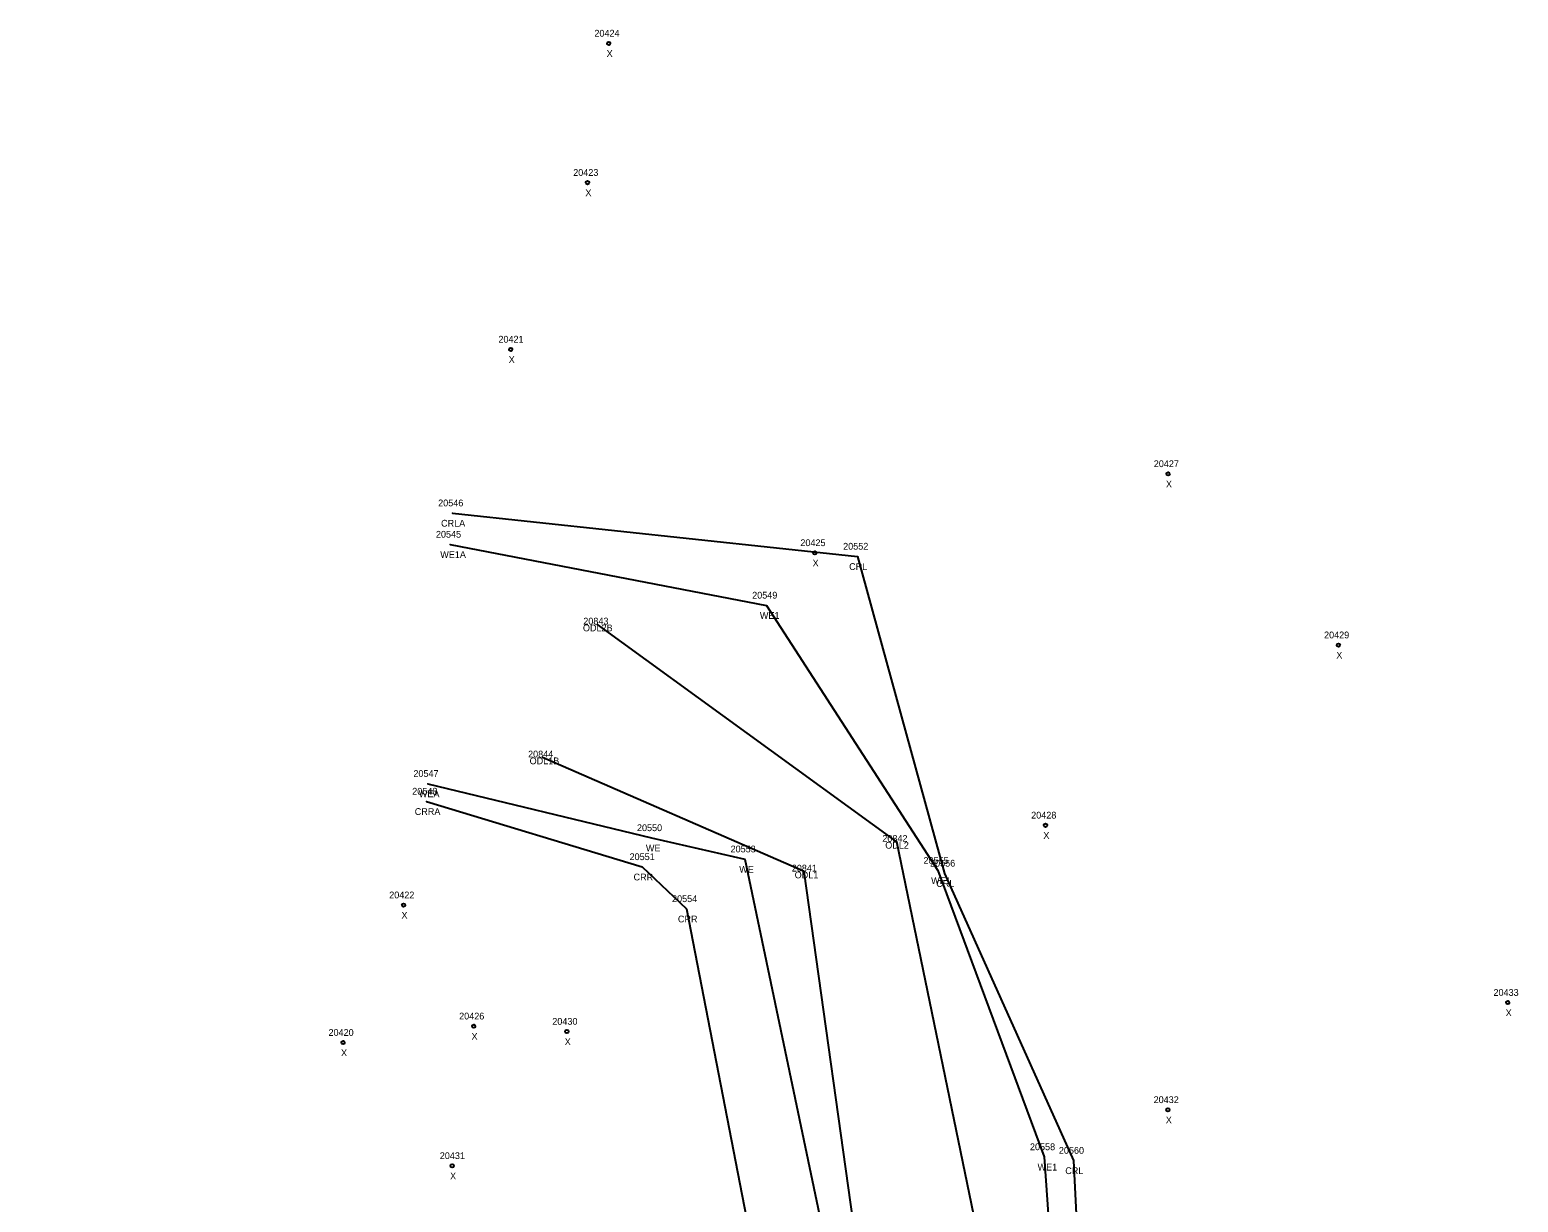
# Model space of a CAD drawing. Extents: x 1966740 to 1969291, y 1117378 to 1118461.
# Drawn here: x 1967789.9 to 1968009.8, y 1118288.2 to 1118461.4 of the extents above; entities that cross this region are included whole.
import ezdxf

# ---------------------------------------------------------------- set-up
doc = ezdxf.new("R2010")
doc.units = 0
for name, color, linetype in [('RD_EX_H2O', 7, 'Continuous'), ('RD_EX_H2O_txCode', 7, 'Continuous'), ('RD_SMD_Locator', 7, 'Continuous'), ('RD_SMD_Misc', 7, 'Continuous')]:
    doc.layers.add(name, color=color, linetype=linetype)

msp = doc.modelspace()

# ---------------------------------------------------------------- linework, layer by layer
at = {"layer": 'RD_EX_H2O'}
for points in [[(1967852.4, 1118390.04), (1967912.21, 1118383.64), (1967925.08, 1118336.82), (1967944.14, 1118294.4), (1967946.67, 1118243.15), (1967961.58, 1118191.28), (1967922.84, 1118148.62), (1967880.18, 1118117.11), (1967858.72, 1118073.64), (1967843.96, 1118030.69), (1967829.77, 1117984.65), (1967829.63, 1117934.73), (1967834.65, 1117903.36)], [(1967852.05, 1118385.41), (1967898.77, 1118376.41), (1967924.08, 1118337.23), (1967939.81, 1118294.93), (1967943.5, 1118242.16), (1967952.29, 1118191.75), (1967920.83, 1118149.81), (1967879.07, 1118118.61), (1967857.7, 1118074.04), (1967841.84, 1118031.93), (1967826.93, 1117984.9), (1967827.73, 1117935.27), (1967832.39, 1117902.59), (1967835.81, 1117893.8), (1967842.37, 1117871.73), (1967853.33, 1117857.05), (1967865.72, 1117824.99), (1967870.38, 1117810.73), (1967864.06, 1117791.33)], [(1967868.55, 1118115.81), (1967902.78, 1118153.01), (1967927.84, 1118168.33), (1967938.95, 1118211.91), (1967931.39, 1118276.79), (1967918, 1118341.48), (1967873.81, 1118373.58)], [(1967855.32, 1118125.6), (1967895.81, 1118162.48), (1967919.58, 1118173.6), (1967923.89, 1118208.71), (1967912.66, 1118277.71), (1967904.34, 1118337.09), (1967865.66, 1118353.94)], [(1967848.72, 1118350.07), (1967881.79, 1118342.06), (1967895.58, 1118338.92), (1967907.43, 1118282.36), (1967910.66, 1118232.56), (1967917.99, 1118192.64), (1967910.91, 1118176.45), (1967849.83, 1118135.18), (1967825.91, 1118086.77), (1967802.99, 1118041.98), (1967795.15, 1117992.28), (1967793.27, 1117935.35), (1967800.64, 1117889.8), (1967800.4, 1117872.52), (1967800.8, 1117854.99), (1967811.67, 1117837.73), (1967837.15, 1117809.04), (1967808.01, 1117752.12)], [(1967848.54, 1118347.45), (1967880.38, 1118337.78), (1967886.93, 1118331.58), (1967896.4, 1118282.85), (1967906.33, 1118232.39), (1967914.38, 1118193.81), (1967904.29, 1118181.59), (1967847.52, 1118139.25), (1967823.99, 1118093.05), (1967800.15, 1118046.69), (1967791.83, 1117992.41), (1967789.93, 1117935.61), (1967798.32, 1117889.19), (1967796.67, 1117880.97)]]:
    msp.add_lwpolyline(points, dxfattribs=at)
at = {"layer": 'RD_SMD_Locator'}
for centre, radius in [((1967875.46, 1118459.42), 0.25), ((1967872.32, 1118438.85), 0.25), ((1967860.99, 1118414.22), 0.25), ((1967958.1, 1118395.83), 0.25), ((1967852.4, 1118390.04), 0.001), ((1967852.05, 1118385.41), 0.001), ((1967905.89, 1118384.16), 0.25), ((1967912.21, 1118383.64), 0.001), ((1967898.77, 1118376.41), 0.001), ((1967873.81, 1118373.58), 0.001), ((1967983.26, 1118370.54), 0.25), ((1967865.66, 1118353.94), 0.001), ((1967848.72, 1118350.07), 0.001), ((1967848.54, 1118347.45), 0.001), ((1967939.99, 1118343.92), 0.25), ((1967881.79, 1118342.06), 0.001), ((1967918, 1118341.48), 0.001), ((1967895.58, 1118338.92), 0.001), ((1967880.38, 1118337.78), 0.001), ((1967904.34, 1118337.09), 0.001), ((1967924.08, 1118337.23), 0.001), ((1967925.08, 1118336.82), 0.001), ((1967845.15, 1118332.13), 0.25), ((1967886.93, 1118331.58), 0.001), ((1968008.28, 1118317.73), 0.25), ((1967855.51, 1118314.24), 0.25), ((1967869.27, 1118313.46), 0.25), ((1967836.22, 1118311.82), 0.25), ((1967958.08, 1118301.89), 0.25), ((1967852.33, 1118293.62), 0.25), ((1967939.81, 1118294.93), 0.001), ((1967944.14, 1118294.4), 0.001)]:
    msp.add_circle(centre, radius, dxfattribs=at)

# ---------------------------------------------------------------- texts
at = {"layer": 'RD_EX_H2O_txCode'}
for s, p in [('20546', (1967850.26, 1118391.04)), ('20545', (1967849.93, 1118386.41)), ('CRLA', (1967850.69, 1118388.04)), ('20552', (1967910.09, 1118384.64)), ('WE1A', (1967850.57, 1118383.41)), ('CRL', (1967910.98, 1118381.64)), ('20549', (1967896.65, 1118377.41)), ('20843', (1967871.7, 1118373.58)), ('WE1', (1967897.79, 1118374.41)), ('ODL2B', (1967871.65, 1118372.58)), ('20844', (1967863.54, 1118353.94)), ('ODL1B', (1967863.77, 1118352.94)), ('20547', (1967846.6, 1118351.07)), ('20548', (1967846.43, 1118348.45)), ('WEA', (1967847.41, 1118348.07)), ('CRRA', (1967846.8, 1118345.45)), ('20550', (1967879.63, 1118343.06)), ('20842', (1967915.88, 1118341.48)), ('ODL2', (1967916.31, 1118340.48)), ('20551', (1967878.54, 1118338.78)), ('WE', (1967880.95, 1118340.06)), ('20553', (1967893.46, 1118339.92)), ('20555', (1967921.96, 1118338.23)), ('CRR', (1967879.13, 1118335.78)), ('WE', (1967894.74, 1118336.92)), ('20841', (1967902.5, 1118337.09)), ('ODL1', (1967902.93, 1118336.09)), ('20556', (1967922.93, 1118337.82)), ('WE1', (1967923.09, 1118335.23)), ('CRL', (1967923.85, 1118334.82)), ('20554', (1967884.81, 1118332.58)), ('CRR', (1967885.68, 1118329.58)), ('20558', (1967937.69, 1118295.93)), ('20560', (1967941.96, 1118295.4)), ('WE1', (1967938.82, 1118292.93)), ('CRL', (1967942.91, 1118292.4))]:
    msp.add_text(s, height=1, dxfattribs=at).set_placement(p)
at = {"layer": 'RD_SMD_Misc'}
for s, p in [('20424', (1967873.34, 1118460.42)), ('X', (1967875.15, 1118457.42)), ('20423', (1967870.21, 1118439.85)), ('X', (1967872.01, 1118436.85)), ('20421', (1967859.16, 1118415.22)), ('X', (1967860.68, 1118412.22)), ('20427', (1967955.98, 1118396.83)), ('X', (1967957.78, 1118393.83)), ('20425', (1967903.77, 1118385.16)), ('X', (1967905.58, 1118382.16)), ('20429', (1967981.14, 1118371.54)), ('X', (1967982.95, 1118368.54)), ('20428', (1967937.87, 1118344.92)), ('X', (1967939.67, 1118341.92)), ('20422', (1967843.03, 1118333.13)), ('X', (1967844.84, 1118330.13)), ('20433', (1968006.17, 1118318.73)), ('20426', (1967853.36, 1118315.24)), ('20430', (1967867.12, 1118314.46)), ('X', (1968007.97, 1118315.73)), ('20420', (1967834.06, 1118312.82)), ('X', (1967855.19, 1118312.24)), ('X', (1967835.91, 1118309.82)), ('X', (1967868.96, 1118311.46)), ('20432', (1967955.96, 1118302.89)), ('X', (1967957.76, 1118299.89)), ('20431', (1967850.5, 1118294.62)), ('X', (1967852.02, 1118291.62))]:
    msp.add_text(s, height=1, dxfattribs=at).set_placement(p)

doc.saveas('drawing.dxf')
